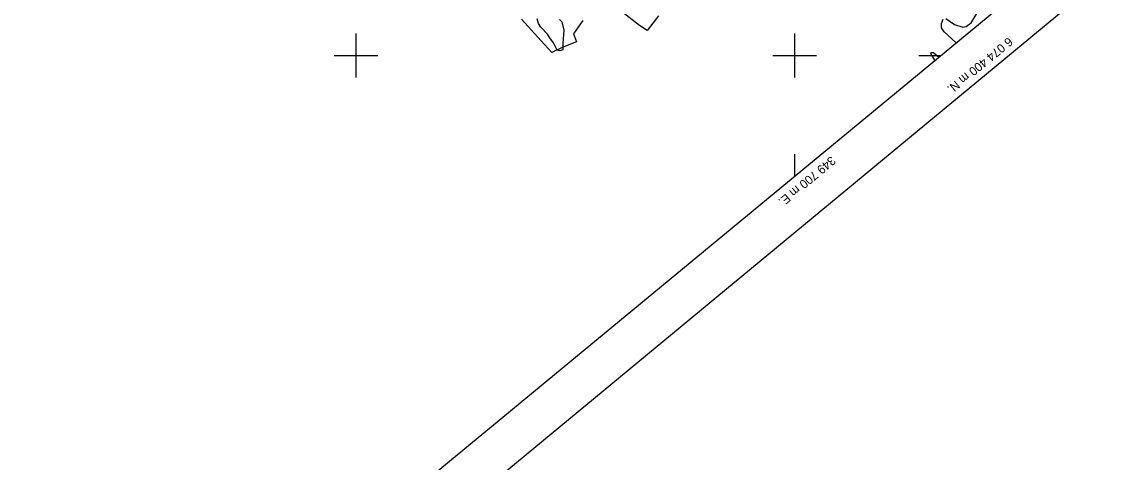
# Model space of a CAD drawing. Extents: x 347312 to 350503, y 6073086 to 6076432.
# Drawn here: x 349347.5 to 349840.3, y 6074214.3 to 6074415.5 of the extents above; entities that cross this region are included whole.
import ezdxf

# ---------------------------------------------------------------- set-up
doc = ezdxf.new("R2010")
doc.units = 0
for name, color, linetype in [('Level 4', 7, 'Continuous'), ('Level 44', 7, 'Continuous'), ('Level 60', 7, 'Continuous'), ('Level 61', 7, 'Continuous')]:
    doc.layers.add(name, color=color, linetype=linetype)

msp = doc.modelspace()

# ---------------------------------------------------------------- linework, layer by layer
at = {"layer": 'Level 4'}
for points in [[(349592.86, 6074416.48), (349593.89, 6074415.33), (349594.71, 6074411.54), (349594.26, 6074405.42), (349594.24, 6074402.57), (349592.94, 6074402.07), (349591.71, 6074402.46), (349590.03, 6074405.74), (349588.42, 6074408.13), (349587.27, 6074409.78), (349584.32, 6074412.97), (349583.21, 6074414.66), (349582.59, 6074416.75)], [(349773.6, 6074405.79), (349768.16, 6074410.74), (349767.05, 6074412.63), (349766.99, 6074414.59), (349767.79, 6074416.6)], [(349769, 6074416.94), (349772.87, 6074414.16), (349776.77, 6074412.89), (349778.22, 6074413.29), (349780.57, 6074414.88), (349783.81, 6074420.35)], [(349763.97, 6074397.83), (349762.07, 6074400.87), (349762.41, 6074401.45), (349763.38, 6074401.45), (349765.72, 6074399.28)]]:
    msp.add_lwpolyline(points, dxfattribs=at)
at = {"layer": 'Level 44'}
for points in [[(349637.87, 6074418.08), (349632.78, 6074411.43), (349629.34, 6074413.76), (349619.87, 6074421.03)], [(349603.38, 6074416), (349599.23, 6074409.83), (349600.52, 6074406.29), (349594.02, 6074403.67), (349589.33, 6074401.38), (349585.94, 6074405.1), (349575.54, 6074416.52)]]:
    msp.add_lwpolyline(points, dxfattribs=at)
at = {"layer": 'Level 60'}
for p, q in [((349756.59, 6074400), (349766.59, 6074400)), ((349700, 6074354.97), (349700, 6074344.97))]:
    msp.add_line(p, q, dxfattribs=at)
for points in [[(348779.44, 6073584.28), (350085.28, 6074663.34), (348652.09, 6076397.74), (347346.25, 6075318.68)], [(350097.64, 6074648.45), (350470.23, 6074198.33), (349166.42, 6073119.09), (348793.83, 6073569.21)]]:
    msp.add_lwpolyline(points, close=True, dxfattribs=at)
at = {"layer": 'Level 61'}
for p, q in [((349500, 6074410), (349500, 6074390)), ((349700, 6074410), (349700, 6074390)), ((349490, 6074400), (349510, 6074400)), ((349690, 6074400), (349710, 6074400))]:
    msp.add_line(p, q, dxfattribs=at)

# ---------------------------------------------------------------- texts
for s, rotation, p in [('6 074 400 m N.', 219.3644, (349797.45, 6074408.59)), ('349 700 m E. ', 219.813, (349716.64, 6074354.31))]:
    msp.add_text(s, height=4, rotation=rotation, dxfattribs=at).set_placement(p)

doc.saveas('drawing.dxf')
